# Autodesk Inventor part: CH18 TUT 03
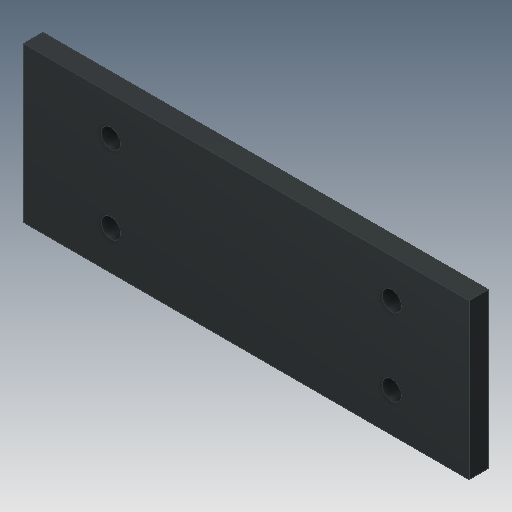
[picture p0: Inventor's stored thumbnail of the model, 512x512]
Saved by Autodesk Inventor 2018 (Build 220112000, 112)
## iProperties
Created: 2016-05
Part Number: CH18 TUT 03
Material: Iron, Cast
Document SubType Name: Modeling
Designer: CADCIM
Density: 7.15 g/cm^3
Appearance: Iron Gray
Mass: 161.642 g
Surface Area: 109.071 cm^2
Volume: 22.6073 cm^3
Author: CADCIM
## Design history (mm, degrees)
sketch "Sketch1"
  geometry: L1 (0, 40)-(115, 40); L2 (115, 40)-(115, 0); L3 (115, 0)-(0, 0); L4 (0, 0)-(0, 40); C1 r 2.5 at (22.5, 30); C2 r 2.5 at (95, 30); C3 r 2.5 at (22.5, 10); C4 r 2.5 at (95, 10); 1 further point
  constraints: 8 end point, 4 centre point, 2 horizontal, 2 parallel, 1 coincident, 1 perpendicular, 1 vertical, 6 other
  dimensions: "d0" = 115 distance of L1.start L1.end; "d1" = 40 distance of L1.end L2.end; "d2" = 10 distance from line of L1 C1.centre; "d3" = 22.5 distance from line of L4 C1.centre; "d6" = 72.5 distance of C1.centre C2.centre; "d9" = 20 distance of C1.centre C3.centre; "d14" = 5 diameter of C2
extrude "Extrusion1" new body sketch "Sketch1" distance "d12" = 5; taper "d13" = 0 deg
body "Solid1"
